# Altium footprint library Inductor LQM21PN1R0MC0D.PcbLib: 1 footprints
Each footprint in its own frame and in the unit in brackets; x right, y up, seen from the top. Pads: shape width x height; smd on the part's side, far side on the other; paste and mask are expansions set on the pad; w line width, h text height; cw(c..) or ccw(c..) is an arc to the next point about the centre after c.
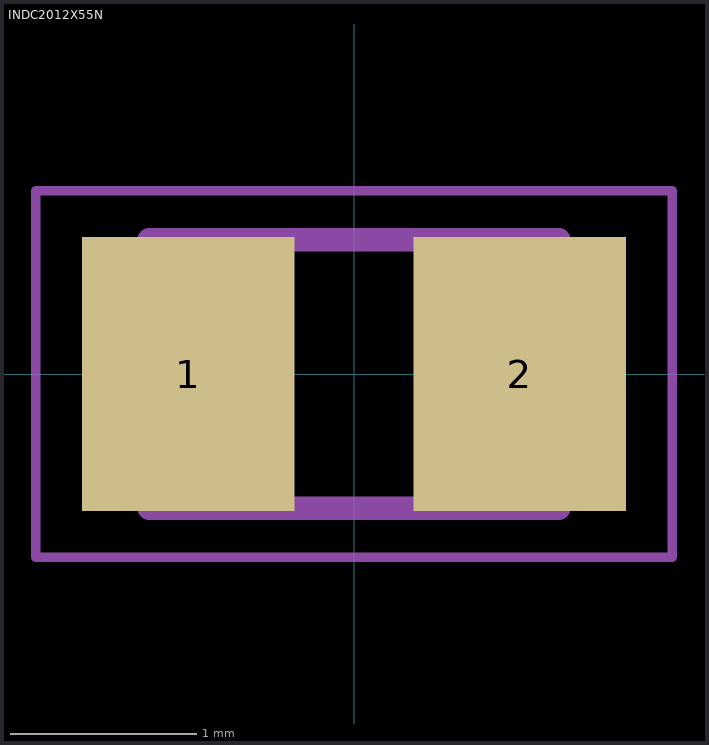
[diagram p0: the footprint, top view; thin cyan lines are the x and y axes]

## INDC2012X55N [mm]
pads (2):
  rect 1.14x1.47 smd: 1(-0.89,0) 2(0.89,0)
Mechanical 13:
  lines w0.127: -1.1,-0.72 -1.1,0.72 1.1,0.72 1.1,-0.72 -1.1,-0.72
Mechanical 15:
  lines w0.05: -1.708,-0.983 -1.708,0.983 1.708,0.983 1.708,-0.983 -1.708,-0.983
